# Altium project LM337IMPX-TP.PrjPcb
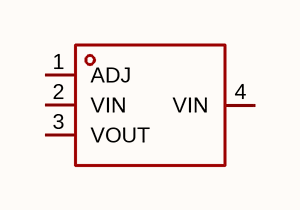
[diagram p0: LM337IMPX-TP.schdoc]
1 sheet, 1 parts. Net scope: global (net labels, ports and power ports of the same name join across sheets).

## Sheet LM337IMPX-TP.schdoc
size 127 x 101 mm

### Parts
U?  lm337impx-tp  [SOT-223_L6.5-W3.5-P2.30-LS7.0-BR]  (value not drawn)

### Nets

Not connected (* = marked no-connect by the designer): U? 1(ADJ) 2(VIN) 3(VOUT) 4(VIN)

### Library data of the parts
U? = lm337impx-tp: 输出极性:负极;工作电压:40V;输出电压:1.2V~37V;输出电流:1.5A;电源纹波抑制比(PSRR):77dB@(120Hz);输出类型:可调;; Manufacturer: TECH PUBLIC(台舟); AddInBom: yes; ModelId: 925194bf9823436183a3e0b978a8d076; ModelName: SOT-223-4P_L6.5-W3.5-H1.6-LS7.0-P2.30; ModelTransform: 279.89794,255.905,0,180,0,0,0.0005,0.0005,0; Output Configuration: 负极; Voltage - Supply: 40V; Output Current: 1.5A; Output Type: 可调; Number of Outputs: 1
